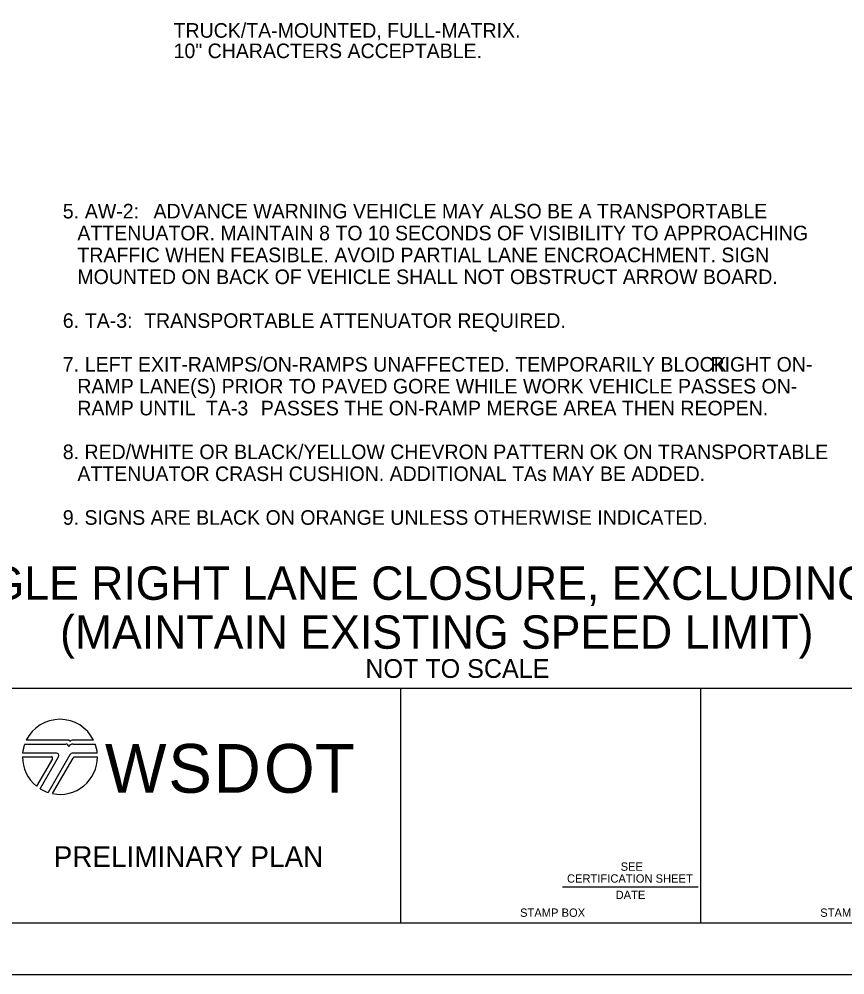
# Model space of a CAD drawing. Extents: x 0 to 17, y 0 to 11.
# Drawn here: x 8.411 to 12.372, y 0 to 4.586 of the extents above; entities that cross this region are included whole.
import ezdxf

# ---------------------------------------------------------------- set-up
doc = ezdxf.new("R2010")
doc.units = 0
for name, color, linetype in [('SH_GI_Logo_WSDOT', 7, 'Continuous'), ('SH_GI_PlotLimits', 7, 'Continuous'), ('SH_GI_SheetBorder1', 7, 'Continuous'), ('SH_GI_SheetBorder3', 7, 'Continuous'), ('SH_GI_SheetTextInCells', 7, 'Continuous'), ('SH_GI_TitleBlockPrelimText', 7, 'Continuous'), ('TR_WZ_PortableChangeMessageSign', 7, 'Continuous'), ('TR_WZ_WorkZoneTextCurrent', 7, 'Continuous')]:
    doc.layers.add(name, color=color, linetype=linetype)

msp = doc.modelspace()

# ---------------------------------------------------------------- linework, layer by layer
at = {"layer": 'SH_GI_Logo_WSDOT'}
for p, q in [((8.4377, 1.1078), (8.6354, 1.1078)), ((8.6489, 1.1258), (8.4454, 1.1258)), ((8.7684, 1.1258), (8.6653, 1.1258)), ((8.6705, 1.1078), (8.776, 1.1078)), ((8.59, 1.0643), (8.4278, 1.0643)), ((8.6541, 1.0553), (8.5502, 0.8754)), ((8.786, 1.0643), (8.6697, 1.0643)), ((8.4269, 1.0463), (8.5657, 1.0463)), ((8.5709, 1.0373), (8.4948, 0.9054)), ((8.5121, 0.8933), (8.6004, 1.0463)), ((8.5713, 0.8698), (8.6697, 1.0403)), ((8.6801, 1.0463), (8.7869, 1.0463))]:
    msp.add_line(p, q, dxfattribs=at)
for centre, radius, start, end in [((8.6069, 1.0463), 0.18, 26.2103, 153.7897), ((8.6069, 1.0463), 0.18, 160.0216, 174.2608), ((8.6354, 1.0943), 0.0135, 360, 90), ((8.6489, 1.1198), 0.006, 0, 90), ((8.6705, 1.0838), 0.024, 90, 154.0555), ((8.6653, 1.1138), 0.012, 90, 150), ((8.6069, 1.0463), 0.18, 5.7392, 19.9784), ((8.59, 1.0523), 0.012, 330, 90), ((8.6697, 1.0463), 0.018, 90, 150), ((8.6069, 1.0463), 0.18, 180, 231.4963), ((8.5657, 1.0403), 0.006, 330, 90), ((8.6069, 1.0463), 0.18, 258.5899, 0), ((8.6801, 1.0343), 0.012, 90, 150), ((8.6069, 1.0463), 0.18, 238.2117, 251.6613)]:
    msp.add_arc(centre, radius, start, end, dxfattribs=at)
at = {"layer": 'SH_GI_PlotLimits'}
msp.add_lwpolyline([(0, 11), (17, 11), (17, 0), (0, 0)], close=True, dxfattribs=at)
at = {"layer": 'SH_GI_SheetBorder1'}
msp.add_line((11.0184, 0.4233), (11.6683, 0.4233), dxfattribs=at)
at = {"layer": 'SH_GI_SheetBorder3'}
for p, q in [((11.68, 1.3759), (11.68, 0.25)), ((1, 1.375), (16.75, 1.375)), ((10.24, 1.375), (10.24, 0.25)), ((1, 0.25), (16.75, 0.25))]:
    msp.add_line(p, q, dxfattribs=at)

# ---------------------------------------------------------------- texts
at = {"layer": 'SH_GI_Logo_WSDOT'}
for s, p in [('W', (8.8225, 0.8739)), ('S', (9.1268, 0.8739)), ('D', (9.3442, 0.8739)), ('O', (9.5854, 0.8739)), ('T', (9.8296, 0.8739))]:
    msp.add_text(s, height=0.234, dxfattribs=at).set_placement(p)
at = {"layer": 'SH_GI_SheetTextInCells'}
for s, p in [('SEE', (11.2966, 0.4995)), ('CERTIFICATION SHEET', (11.0393, 0.4425)), ('DATE', (11.2723, 0.3641)), ('STAMP BOX', (10.8141, 0.2786)), ('STAMP BOX', (12.2541, 0.2786))]:
    msp.add_text(s, height=0.04, dxfattribs=at).set_placement(p)
at = {"layer": 'SH_GI_TitleBlockPrelimText'}
msp.add_text('PRELIMINARY PLAN', height=0.1, dxfattribs=at).set_placement((8.5768, 0.5173))
at = {"layer": 'TR_WZ_PortableChangeMessageSign'}
for s, p in [('TRUCK/TA-MOUNTED, FULL-MATRIX.', (9.152, 4.4968)), ('10" CHARACTERS ACCEPTABLE.', (9.152, 4.3988))]:
    msp.add_text(s, height=0.07, rotation=360, dxfattribs=at).set_placement(p)
at = {"layer": 'TR_WZ_WorkZoneTextCurrent'}
for s, height, p in [('5. ', 0.07, (8.6204, 3.6297)), ('AW-2:', 0.07, (8.7261, 3.6297)), (' ADVANCE WARNING VEHICLE MAY ALSO BE A TRANSPORTABLE ', 0.07, (9.0297, 3.6297)), ('ATTENUATOR. MAINTAIN 8 TO 10 SECONDS OF VISIBILITY TO APPROACHING ', 0.07, (8.6904, 3.5247)), ('TRAFFIC WHEN FEASIBLE. AVOID PARTIAL LANE ENCROACHMENT. SIGN ', 0.07, (8.6904, 3.4197)), ('MOUNTED ON BACK OF VEHICLE SHALL NOT OBSTRUCT ARROW BOARD.', 0.07, (8.6904, 3.3147)), ('6. ', 0.07, (8.6204, 3.1047)), ('TA-3:', 0.07, (8.7261, 3.1047)), (' TRANSPORTABLE ATTENUATOR REQUIRED.', 0.07, (8.9846, 3.1047)), ('7. ', 0.07, (8.6204, 2.8947)), ('LEFT EXIT-RAMPS/ON-RAMPS UNAFFECTED. TEMPORARILY BLOCK ', 0.07, (8.7261, 2.8947)), ('RIGHT ON-', 0.07, (11.7276, 2.8947)), ('RAMP LANE(S) PRIOR TO PAVED GORE WHILE WORK VEHICLE PASSES ON-', 0.07, (8.6904, 2.7897)), ('RAMP UNTIL ', 0.07, (8.6904, 2.6847)), ('TA-3', 0.07, (9.3072, 2.6847)), (' PASSES THE ON-RAMP MERGE AREA THEN REOPEN.', 0.07, (9.5444, 2.6847)), ('8. RED/WHITE OR BLACK/YELLOW CHEVRON PATTERN OK ON TRANSPORTABLE ', 0.07, (8.6204, 2.4747)), ('ATTENUATOR CRASH CUSHION. ADDITIONAL TAs MAY BE ADDED.', 0.07, (8.6904, 2.3697)), ('9. SIGNS ARE BLACK ON ORANGE UNLESS OTHERWISE INDICATED.', 0.07, (8.6204, 2.1597)), ('FREEWAY (2+ LANES): MOBILE SINGLE RIGHT LANE CLOSURE, EXCLUDING PAVEMENT MARKING OPERATIONS', 0.16, (4.6606, 1.7997)), ('(MAINTAIN EXISTING SPEED LIMIT)', 0.16, (8.6073, 1.565)), ('NOT TO SCALE', 0.09, (10.0722, 1.425))]:
    msp.add_text(s, height=height, rotation=360, dxfattribs=at).set_placement(p)

doc.saveas('drawing.dxf')
